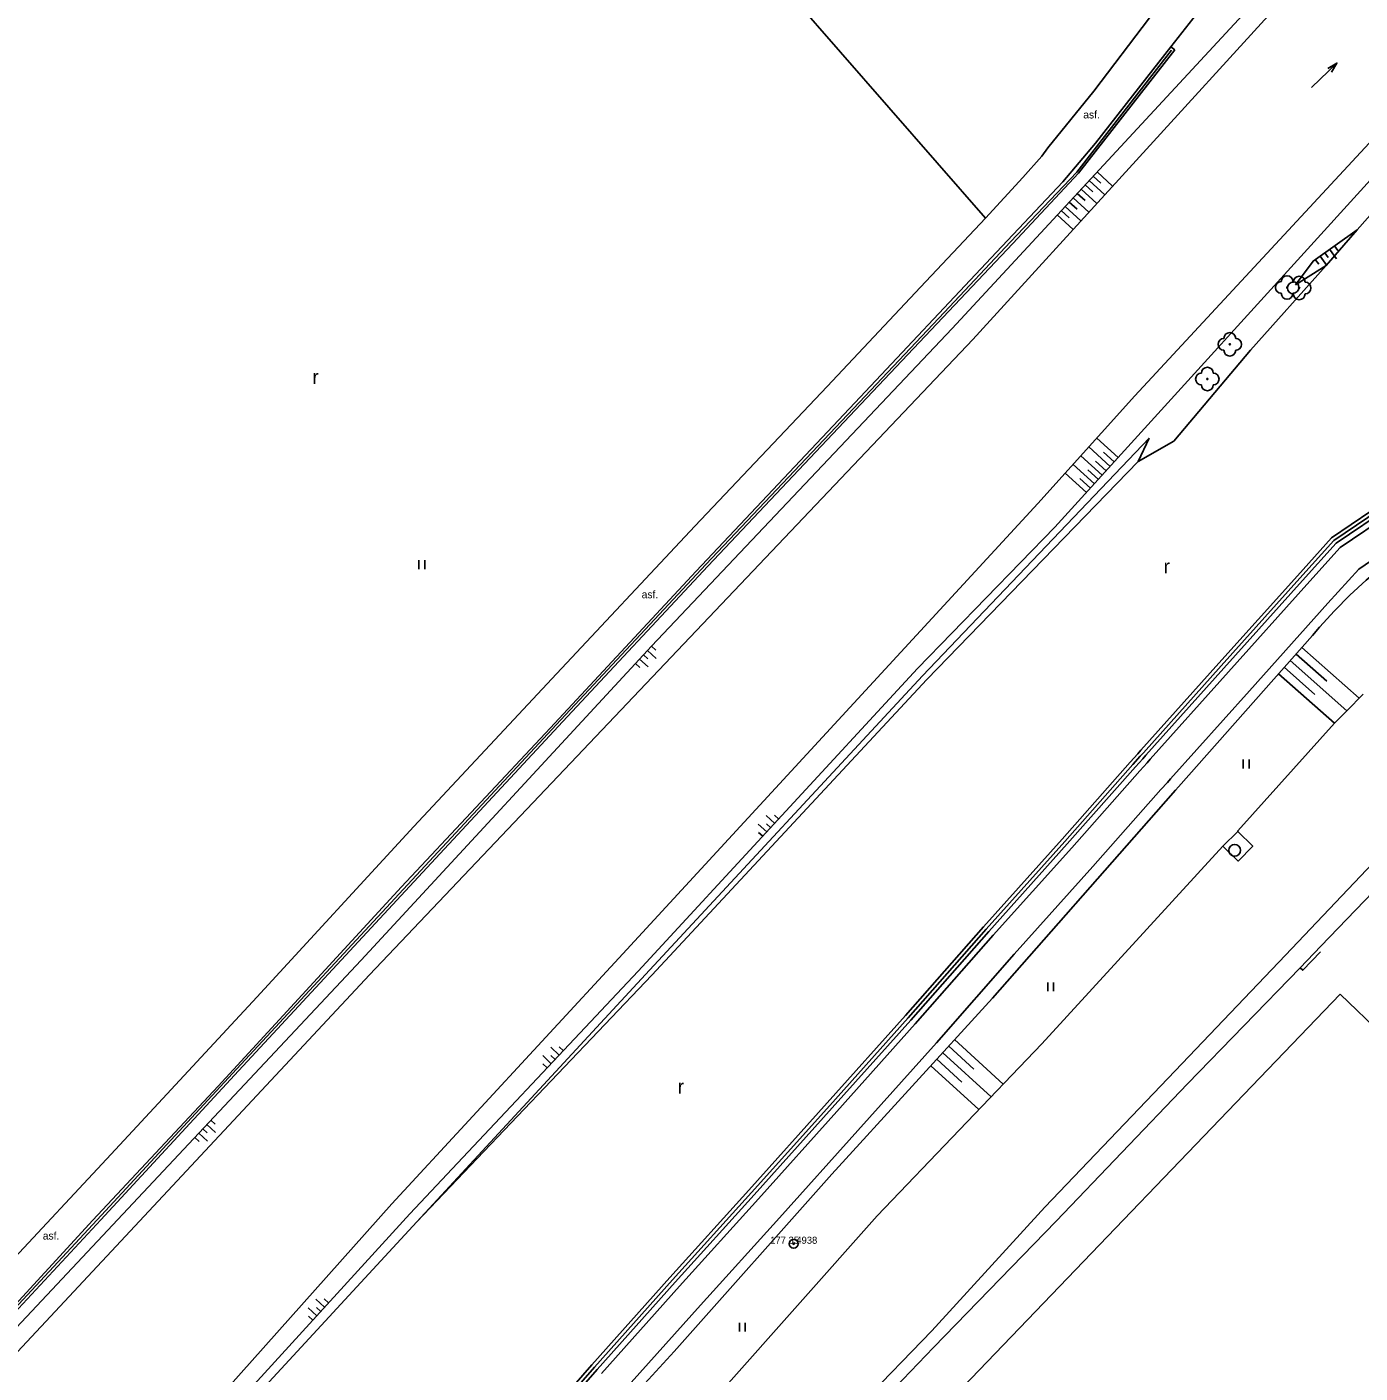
# Model space of a CAD drawing. Extents: x -538441 to -536770, y -1181008 to -1179809.
# Drawn here: x -537869.9 to -537756.6, y -1180204.6 to -1180090.1 of the extents above; entities that cross this region are included whole.
import ezdxf

# ---------------------------------------------------------------- set-up
doc = ezdxf.new("R2010")
doc.units = 0
for name, color, linetype in [('Vrstva 10', 7, 'Continuous'), ('Vrstva 11', 7, 'Continuous'), ('Vrstva 14', 7, 'Continuous'), ('Vrstva 15', 7, 'Continuous'), ('Vrstva 21', 7, 'Continuous'), ('Vrstva 22', 7, 'Continuous'), ('Vrstva 23', 7, 'Continuous'), ('Vrstva 27', 7, 'Continuous'), ('Vrstva 36', 7, 'Continuous'), ('Vrstva 40', 7, 'Continuous'), ('Vrstva 45', 7, 'Continuous'), ('Vrstva 5', 7, 'Continuous'), ('Vrstva 7', 7, 'Continuous'), ('Vrstva 9', 7, 'Continuous')]:
    doc.layers.add(name, color=color, linetype=linetype)

msp = doc.modelspace()

# ---------------------------------------------------------------- linework, layer by layer
at = {"layer": 'Vrstva 10'}
for p, q in [((-537770.203, -1180088.675), (-537772.694, -1180091.825)), ((-537779.225, -1180095.618), (-537774.489, -1180089.383)), ((-537774.735, -1180094.46), (-537772.694, -1180091.825)), ((-537779.081, -1180100.02), (-537774.735, -1180094.46)), ((-537783.128, -1180100.424), (-537779.225, -1180095.618)), ((-537781.878, -1180103.31), (-537779.081, -1180100.02)), ((-537787.492, -1180109.305), (-537781.878, -1180103.31)), ((-537799.558, -1180122.105), (-537787.492, -1180109.305)), ((-537813.138, -1180132.602), (-537801.907, -1180120.726)), ((-537813.048, -1180136.438), (-537799.558, -1180122.105)), ((-537825.319, -1180145.598), (-537813.138, -1180132.602)), ((-537825.442, -1180149.768), (-537813.048, -1180136.438)), ((-537837.033, -1180158.137), (-537825.319, -1180145.598)), ((-537838.084, -1180163.285), (-537825.442, -1180149.768)), ((-537850.397, -1180172.65), (-537837.033, -1180158.137)), ((-537853.671, -1180180.234), (-537838.084, -1180163.285)), ((-537862.762, -1180186.022), (-537850.397, -1180172.65)), ((-537864.325, -1180191.635), (-537853.671, -1180180.234)), ((-537871.768, -1180195.642), (-537862.762, -1180186.022)), ((-537875.133, -1180203.393), (-537864.325, -1180191.635))]:
    msp.add_line(p, q, dxfattribs=at)
for points in [[(-537788.432, -1180106.398), (-537785.272, -1180102.943), (-537783.65, -1180101.15), (-537783.128, -1180100.424)], [(-537801.907, -1180120.726), (-537793.98, -1180112.27), (-537788.432, -1180106.398)]]:
    msp.add_lwpolyline(points, dxfattribs=at)
at = {"layer": 'Vrstva 11'}
for p, q in [((-537772.348, -1180092.094), (-537780.526, -1180102.586)), ((-537772.694, -1180091.825), (-537772.348, -1180092.094)), ((-537780.526, -1180102.586), (-537786.131, -1180108.556)), ((-537786.131, -1180108.556), (-537798.517, -1180121.696)), ((-537798.517, -1180121.696), (-537812.037, -1180136.016)), ((-537759.032, -1180133.594), (-537752.242, -1180128.979)), ((-537758.303, -1180134.428), (-537751.623, -1180129.888)), ((-537756.712, -1180136.249), (-537750.273, -1180131.873)), ((-537761.928, -1180136.82), (-537759.032, -1180133.594)), ((-537761.11, -1180137.555), (-537758.303, -1180134.428)), ((-537812.037, -1180136.016), (-537824.366, -1180149.216)), ((-537768.615, -1180144.266), (-537761.928, -1180136.82)), ((-537759.324, -1180139.158), (-537756.712, -1180136.249)), ((-537767.796, -1180145), (-537761.11, -1180137.555)), ((-537766.009, -1180146.602), (-537759.324, -1180139.158)), ((-537775.233, -1180151.663), (-537768.615, -1180144.266)), ((-537774.441, -1180152.427), (-537767.796, -1180145)), ((-537772.712, -1180154.094), (-537766.009, -1180146.602)), ((-537824.366, -1180149.216), (-537836.664, -1180162.463)), ((-537781.932, -1180159.225), (-537776.147, -1180152.685)), ((-537781.111, -1180159.957), (-537775.325, -1180153.416)), ((-537779.319, -1180161.553), (-537773.532, -1180155.011)), ((-537788.607, -1180166.665), (-537781.932, -1180159.225)), ((-537787.784, -1180167.395), (-537781.111, -1180159.957)), ((-537762.941, -1180169.078), (-537754.422, -1180160.13)), ((-537785.99, -1180168.989), (-537779.319, -1180161.553)), ((-537836.664, -1180162.463), (-537852.286, -1180179.3)), ((-537795.237, -1180174.208), (-537788.607, -1180166.665)), ((-537794.414, -1180174.938), (-537787.784, -1180167.395)), ((-537792.619, -1180176.531), (-537785.99, -1180168.989)), ((-537772.318, -1180178.923), (-537762.941, -1180169.078)), ((-537761.688, -1180170.158), (-537771.273, -1180180.024)), ((-537801.909, -1180181.657), (-537795.237, -1180174.208)), ((-537801.09, -1180182.391), (-537794.414, -1180174.938)), ((-537799.302, -1180183.992), (-537792.619, -1180176.531)), ((-537852.286, -1180179.3), (-537863.652, -1180191.591)), ((-537783.401, -1180190.507), (-537772.318, -1180178.923)), ((-537771.273, -1180180.024), (-537782.443, -1180191.716)), ((-537808.551, -1180189.069), (-537801.909, -1180181.657)), ((-537807.734, -1180189.805), (-537801.09, -1180182.391)), ((-537805.95, -1180191.411), (-537799.302, -1180183.992)), ((-537815.276, -1180196.503), (-537808.551, -1180189.069)), ((-537814.458, -1180197.238), (-537807.734, -1180189.805)), ((-537792.994, -1180201.034), (-537783.401, -1180190.507)), ((-537863.652, -1180191.591), (-537875.72, -1180204.586)), ((-537812.672, -1180198.842), (-537805.95, -1180191.411)), ((-537782.443, -1180191.716), (-537792.851, -1180202.463)), ((-537821.907, -1180203.935), (-537815.276, -1180196.503)), ((-537821.084, -1180204.665), (-537814.458, -1180197.238)), ((-537819.288, -1180206.257), (-537812.672, -1180198.842)), ((-537803.9, -1180212.27), (-537792.994, -1180201.034)), ((-537792.851, -1180202.463), (-537803.281, -1180213.291)), ((-537828.549, -1180211.477), (-537821.907, -1180203.935))]:
    msp.add_line(p, q, dxfattribs=at)
for points in [[(-537776.147, -1180152.685), (-537775.5, -1180151.962), (-537775.233, -1180151.663)], [(-537775.325, -1180153.416), (-537774.708, -1180152.726), (-537774.441, -1180152.427)], [(-537773.532, -1180155.011), (-537772.979, -1180154.393), (-537772.712, -1180154.094)], [(-537766.99, -1180158.57), (-537765.72, -1180159.82), (-537766.965, -1180161.085), (-537768.25, -1180159.82), (-537766.99, -1180158.57)]]:
    msp.add_lwpolyline(points, dxfattribs=at)
at = {"layer": 'Vrstva 14'}
for p, q in [((-537775.75, -1180121.53), (-537737.82, -1180080.6)), ((-537782.534, -1180132.691), (-537736.85, -1180082.34)), ((-537788.432, -1180106.398), (-537806.23, -1180086.02)), ((-537791.27, -1180115.78), (-537763.85, -1180086.17)), ((-537762.59, -1180087.2), (-537789.523, -1180116.72)), ((-537816.843, -1180142.799), (-537791.27, -1180115.78)), ((-537840.8, -1180170.77), (-537789.523, -1180116.72)), ((-537783.982, -1180130.676), (-537775.75, -1180121.53)), ((-537783.982, -1180130.676), (-537819.28, -1180168.98)), ((-537782.534, -1180132.691), (-537794.21, -1180144.71)), ((-537841.52, -1180169.52), (-537816.843, -1180142.799)), ((-537760.64, -1180141.89), (-537772.021, -1180154.761)), ((-537794.21, -1180144.71), (-537817.96, -1180170.45)), ((-537758.778, -1180149.368), (-537766.99, -1180158.51)), ((-537773.93, -1180156.92), (-537787.85, -1180172.75)), ((-537766.99, -1180158.51), (-537766.99, -1180158.57)), ((-537783.64, -1180176.62), (-537768.25, -1180159.82)), ((-537819.28, -1180168.98), (-537838.9, -1180190.23)), ((-537872.13, -1180202.15), (-537841.52, -1180169.52)), ((-537871.14, -1180203.25), (-537840.8, -1180170.77)), ((-537817.96, -1180170.45), (-537837.37, -1180191.08)), ((-537787.85, -1180172.75), (-537801.51, -1180187.71)), ((-537783.64, -1180176.62), (-537797.66, -1180191.24)), ((-537801.51, -1180187.71), (-537814.92, -1180202.78)), ((-537838.9, -1180190.23), (-537856.91, -1180210.4)), ((-537837.37, -1180191.08), (-537856, -1180211.47)), ((-537797.66, -1180191.24), (-537810.98, -1180206.25)), ((-537814.92, -1180202.78), (-537828.2, -1180217.27))]:
    msp.add_line(p, q, dxfattribs=at)
for points in [[(-537762.09, -1180112.08), (-537760.59, -1180110.06), (-537756.85, -1180107.39)], [(-537756.85, -1180107.39), (-537759.48, -1180110.43), (-537762.09, -1180112.08)], [(-537751.65, -1180133.76), (-537753.176, -1180134.844), (-537754.654, -1180135.993), (-537756.082, -1180137.203), (-537757.456, -1180138.473), (-537758.776, -1180139.801)], [(-537758.776, -1180139.801), (-537760.037, -1180141.184), (-537760.64, -1180141.89)], [(-537756.32, -1180146.89), (-537757.72, -1180148.301), (-537758.778, -1180149.368)], [(-537772.021, -1180154.761), (-537772.286, -1180155.061), (-537773.93, -1180156.92)]]:
    msp.add_lwpolyline(points, dxfattribs=at)
at = {"layer": 'Vrstva 15'}
for p, q in [((-537779.284, -1180102.836), (-537778.626, -1180103.446)), ((-537778.944, -1180102.47), (-537777.631, -1180103.686)), ((-537780.303, -1180103.937), (-537778.979, -1180105.163)), ((-537779.964, -1180103.57), (-537779.303, -1180104.182)), ((-537779.624, -1180103.203), (-537778.305, -1180104.424)), ((-537781.322, -1180105.038), (-537780.656, -1180105.655)), ((-537780.982, -1180104.671), (-537779.653, -1180105.902)), ((-537780.642, -1180104.304), (-537779.979, -1180104.918)), ((-537782.342, -1180106.138), (-537781.001, -1180107.38)), ((-537782.002, -1180105.771), (-537781.333, -1180106.391)), ((-537781.662, -1180105.404), (-537780.327, -1180106.64)), ((-537759.996, -1180109.636), (-537759.415, -1180110.449)), ((-537759.589, -1180109.345), (-537759.298, -1180109.752)), ((-537759.182, -1180109.054), (-537758.601, -1180109.868)), ((-537758.775, -1180108.764), (-537758.485, -1180109.171)), ((-537760.403, -1180109.926), (-537760.112, -1180110.333)), ((-537777.166, -1180126.775), (-537778.985, -1180125.124)), ((-537778.51, -1180128.256), (-537780.323, -1180126.611)), ((-537777.838, -1180127.515), (-537779.654, -1180125.867)), ((-537777.502, -1180127.145), (-537778.411, -1180126.32)), ((-537779.182, -1180128.997), (-537780.992, -1180127.354)), ((-537778.846, -1180128.626), (-537779.751, -1180127.804)), ((-537778.174, -1180127.886), (-537779.081, -1180127.062)), ((-537779.854, -1180129.737), (-537781.661, -1180128.097)), ((-537779.518, -1180129.367), (-537780.422, -1180128.546)), ((-537816.843, -1180142.799), (-537816.476, -1180143.138)), ((-537817.86, -1180143.901), (-537817.125, -1180144.579)), ((-537817.521, -1180143.534), (-537817.154, -1180143.873)), ((-537817.182, -1180143.167), (-537816.447, -1180143.845)), ((-537757.72, -1180148.301), (-537762.54, -1180144.039)), ((-537759.436, -1180145.783), (-537762.043, -1180143.477)), ((-537756.662, -1180147.235), (-537761.547, -1180142.915)), ((-537818.199, -1180144.269), (-537817.832, -1180144.608)), ((-537758.778, -1180149.368), (-537763.534, -1180145.163)), ((-537760.429, -1180146.907), (-537763.037, -1180144.601)), ((-537806.359, -1180157.877), (-537807.094, -1180157.198)), ((-537806.02, -1180157.509), (-537806.387, -1180157.17)), ((-537807.037, -1180158.611), (-537807.772, -1180157.933)), ((-537807.376, -1180158.979), (-537807.744, -1180158.64)), ((-537806.698, -1180158.244), (-537807.065, -1180157.905)), ((-537824.673, -1180177.586), (-537825.402, -1180176.901)), ((-537824.331, -1180177.222), (-537824.695, -1180176.879)), ((-537789.437, -1180178.773), (-537791.571, -1180176.825)), ((-537786.928, -1180180.048), (-537791.065, -1180176.271)), ((-537825.359, -1180178.314), (-537826.087, -1180177.629)), ((-537825.701, -1180178.678), (-537826.065, -1180178.336)), ((-537825.016, -1180177.95), (-537825.38, -1180177.607)), ((-537790.448, -1180179.881), (-537792.582, -1180177.932)), ((-537787.966, -1180181.131), (-537792.076, -1180177.379)), ((-537789.005, -1180182.214), (-537793.088, -1180178.486)), ((-537854.972, -1180183.859), (-537854.608, -1180184.201)), ((-537854.63, -1180183.495), (-537853.9, -1180184.179)), ((-537854.288, -1180183.129), (-537853.924, -1180183.471)), ((-537855.656, -1180184.589), (-537855.292, -1180184.931)), ((-537855.314, -1180184.223), (-537854.584, -1180184.907)), ((-537844.623, -1180199.018), (-537845.361, -1180198.343)), ((-537844.285, -1180198.649), (-537844.655, -1180198.311)), ((-537845.297, -1180199.756), (-537846.036, -1180199.082)), ((-537845.635, -1180200.125), (-537846.004, -1180199.788)), ((-537844.96, -1180199.387), (-537845.329, -1180199.05))]:
    msp.add_line(p, q, dxfattribs=at)
at = {"layer": 'Vrstva 21'}
for radius in [0.375, 0.05]:
    msp.add_circle((-537804.749, -1180193.628), radius, dxfattribs=at)
at = {"layer": 'Vrstva 22'}
for centre in [(-537762.8, -1180112.3), (-537761.77, -1180112.35), (-537767.67, -1180117.14), (-537769.58, -1180120.09)]:
    msp.add_circle(centre, 0.05, dxfattribs=at)
for centre, start, end in [((-537763.3, -1180112.3), 90, 270), ((-537762.8, -1180111.8), 0, 180), ((-537762.27, -1180112.35), 90, 270), ((-537762.3, -1180112.3), 270, 90), ((-537761.77, -1180111.85), 0, 180), ((-537761.27, -1180112.35), 270, 90), ((-537762.8, -1180112.8), 180, 0), ((-537761.77, -1180112.85), 180, 0), ((-537767.67, -1180116.64), 0, 180), ((-537768.17, -1180117.14), 90, 270), ((-537767.67, -1180117.64), 180, 0), ((-537767.17, -1180117.14), 270, 90), ((-537770.08, -1180120.09), 90, 270), ((-537769.58, -1180119.59), 0, 180), ((-537769.08, -1180120.09), 270, 90), ((-537769.58, -1180120.59), 180, 0)]:
    msp.add_arc(centre, 0.5, start, end, dxfattribs=at)
at = {"layer": 'Vrstva 23'}
for p, q in [((-537728.21, -1180075.02), (-537756.85, -1180107.39)), ((-537765.91, -1180117.63), (-537759.48, -1180110.43)), ((-537772.43, -1180125.38), (-537765.91, -1180117.63)), ((-537793.79, -1180145.32), (-537774.53, -1180125.12)), ((-537774.53, -1180125.12), (-537775.46, -1180127.11)), ((-537775.46, -1180127.11), (-537772.43, -1180125.38)), ((-537775.46, -1180127.11), (-537793.44, -1180145.65)), ((-537817.34, -1180170.74), (-537793.79, -1180145.32)), ((-537793.44, -1180145.65), (-537816.8, -1180170.78)), ((-537836.78, -1180191.75), (-537817.34, -1180170.74)), ((-537816.8, -1180170.78), (-537836.78, -1180191.75)), ((-537855.3, -1180211.82), (-537836.78, -1180191.75))]:
    msp.add_line(p, q, dxfattribs=at)
at = {"layer": 'Vrstva 27'}
msp.add_circle((-537767.26, -1180160.17), 0.5, dxfattribs=at)
at = {"layer": 'Vrstva 36'}
for p, q in [((-537836.611, -1180136.25), (-537836.611, -1180135.5)), ((-537836.11, -1180136.25), (-537836.11, -1180135.5)), ((-537766.534, -1180153.199), (-537766.534, -1180152.449)), ((-537766.034, -1180153.199), (-537766.034, -1180152.449)), ((-537783.149, -1180172.146), (-537783.149, -1180171.396)), ((-537782.649, -1180172.146), (-537782.649, -1180171.396)), ((-537809.368, -1180201.096), (-537809.368, -1180200.346)), ((-537808.868, -1180201.096), (-537808.868, -1180200.346))]:
    msp.add_line(p, q, dxfattribs=at)
at = {"layer": 'Vrstva 45'}
msp.add_line((-537760.72, -1180095.311), (-537758.561, -1180093.228), dxfattribs=at)
msp.add_lwpolyline([(-537759.351, -1180093.671), (-537758.561, -1180093.228), (-537759.032, -1180094.002)], dxfattribs=at)
at = {"layer": 'Vrstva 5'}
for p, q in [((-537758.298, -1180172.409), (-537819.295, -1180235.955)), ((-537754.691, -1180175.872), (-537758.298, -1180172.409))]:
    msp.add_line(p, q, dxfattribs=at)
at = {"layer": 'Vrstva 7'}
for p, q in [((-537758.833, -1180133.822), (-537752.073, -1180129.227)), ((-537758.634, -1180134.05), (-537751.904, -1180129.475)), ((-537761.705, -1180137.02), (-537758.833, -1180133.822)), ((-537761.482, -1180137.22), (-537758.634, -1180134.05)), ((-537768.392, -1180144.466), (-537761.705, -1180137.02)), ((-537768.169, -1180144.666), (-537761.482, -1180137.22)), ((-537775.017, -1180151.871), (-537768.392, -1180144.466)), ((-537774.801, -1180152.079), (-537768.169, -1180144.666)), ((-537781.708, -1180159.425), (-537775.923, -1180152.884)), ((-537781.484, -1180159.625), (-537775.699, -1180153.083)), ((-537788.383, -1180166.864), (-537781.708, -1180159.425)), ((-537788.159, -1180167.063), (-537781.484, -1180159.625)), ((-537759.932, -1180168.323), (-537753.07, -1180161.18)), ((-537795.013, -1180174.407), (-537788.383, -1180166.864)), ((-537794.789, -1180174.606), (-537788.159, -1180167.063)), ((-537759.932, -1180168.323), (-537761.688, -1180170.158)), ((-537801.686, -1180181.857), (-537795.013, -1180174.407)), ((-537801.463, -1180182.057), (-537794.789, -1180174.606)), ((-537808.328, -1180189.27), (-537801.686, -1180181.857)), ((-537808.105, -1180189.471), (-537801.463, -1180182.057)), ((-537815.053, -1180196.704), (-537808.328, -1180189.27)), ((-537814.83, -1180196.905), (-537808.105, -1180189.471)), ((-537821.683, -1180204.134), (-537815.053, -1180196.704)), ((-537821.459, -1180204.333), (-537814.83, -1180196.905)), ((-537828.325, -1180211.676), (-537821.683, -1180204.134)), ((-537828.101, -1180211.875), (-537821.459, -1180204.333))]:
    msp.add_line(p, q, dxfattribs=at)
for points in [[(-537775.923, -1180152.884), (-537775.284, -1180152.17), (-537775.017, -1180151.871)], [(-537775.699, -1180153.083), (-537775.069, -1180152.378), (-537774.801, -1180152.079)], [(-537759.964, -1180168.794), (-537761.471, -1180170.366), (-537761.688, -1180170.158)]]:
    msp.add_lwpolyline(points, dxfattribs=at)
at = {"layer": 'Vrstva 9'}
for p, q in [((-537772.62, -1180092.12), (-537780.68, -1180102.5)), ((-537780.68, -1180102.5), (-537786.313, -1180108.414)), ((-537798.684, -1180121.538), (-537812.21, -1180135.864)), ((-537812.21, -1180135.864), (-537824.546, -1180149.071)), ((-537824.546, -1180149.071), (-537836.833, -1180162.307)), ((-537836.833, -1180162.307), (-537852.455, -1180179.144)), ((-537852.455, -1180179.144), (-537863.601, -1180191.197)), ((-537863.601, -1180191.197), (-537875.892, -1180204.433))]:
    msp.add_line(p, q, dxfattribs=at)
msp.add_lwpolyline([(-537786.313, -1180108.414), (-537791.96, -1180114.42), (-537798.684, -1180121.538)], dxfattribs=at)

# ---------------------------------------------------------------- texts
at = {"layer": 'Vrstva 22'}
msp.add_text('177 35 ', height=0.6, dxfattribs=at).set_placement((-537806.749, -1180193.628))
at = {"layer": 'Vrstva 23'}
msp.add_text(' 4938', height=0.6, dxfattribs=at).set_placement((-537804.749, -1180193.628))
at = {"layer": 'Vrstva 36'}
for p in [(-537845.658, -1180120.504), (-537773.302, -1180136.624), (-537814.602, -1180180.854)]:
    msp.add_text('r', height=1.2, dxfattribs=at).set_placement(p)
at = {"layer": 'Vrstva 40'}
for p in [(-537780.127, -1180097.929), (-537817.669, -1180138.733), (-537868.582, -1180193.269)]:
    msp.add_text('asf.', height=0.65, dxfattribs=at).set_placement(p)

doc.saveas('drawing.dxf')
